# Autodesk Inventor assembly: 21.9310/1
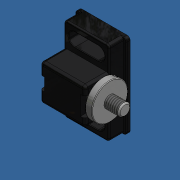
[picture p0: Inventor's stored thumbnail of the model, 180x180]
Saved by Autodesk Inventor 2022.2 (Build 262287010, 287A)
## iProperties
Company: CADENAS
Created: 2022-08
Part Number: 21.9310/1
Description: MAGNETIC CATCH 30 SUBCOMPONENT
Document SubType Name: Assembly
Designer: amoles
Vendor: V
Sending System: PARTsolutions
Preprocessor: ST-DEVELOPER v18.102
Title: 093094
Author: License CC BY-ND 4.0
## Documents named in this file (3)
- L:\INVENTOR LIBRARIES\PARTS LIBRARY\30 SERIES\SUBCOMPONENTS\21.9310_1 MAGNETIC CATCH 30.iam
- L:\INVENTOR LIBRARIES\PARTS LIBRARY\30 SERIES\SUBCOMPONENTS\21.9310 MAGNETIC CATCH 30 SCREW.ipt
- L:\INVENTOR LIBRARIES\PARTS LIBRARY\30 SERIES\SUBCOMPONENTS\21.9310 MAGNETIC CATCH 30 BODY.ipt
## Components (2 placed, 2 different names)
1. NAUO2 — Mate:1, Mate:3, Mate:4
2. NAUO1 — Mate:1, Mate:3, Mate:4
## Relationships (3: Mate 3)
- Mate:1: NAUO2 ↔ NAUO1
- Mate:3: NAUO2 ↔ NAUO1
- Mate:4: NAUO2 ↔ NAUO1
